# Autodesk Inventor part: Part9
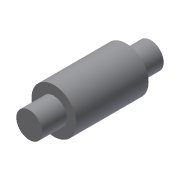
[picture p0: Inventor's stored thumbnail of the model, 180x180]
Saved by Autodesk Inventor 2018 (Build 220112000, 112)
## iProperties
Shininess: 77.0
Length Units: 11269
Angle Units: 11279
Time Units: 11290
Mass Units: 11283
Length Display Precision: 3
Angle Display Precision: 2
Created: 2002-01
Part Number: Part9
Document SubType Name: Modeling
Designer: ***
Density: 1 g/cm^3
Material: Generic
Appearance: Default
Density: 0.0
Volumn: 0.0
Area: 0.0
PropertySet Name: Model Information
Control State: 0
Master: False
Checked Out: False
Author: ***
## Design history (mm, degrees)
sketch "Sketch1"
  geometry: L1 (0.279, 23.245)-(5.19, 23.245); L2 (5.19, 23.245)-(5.19, 13.947); L3 (5.19, 13.947)-(8.761, 13.947); L4 (8.761, 13.947)-(8.761, -13.295); L5 (8.761, -13.295)-(5.19, -13.295); L6 (5.19, -13.295)-(5.19, -22.592); L7 (5.19, -22.592)-(0.279, -22.592); L8 (0.279, -22.592)-(0.279, 23.245)
  constraints: 16 end point, 5 parallel, 2 equal length, 1 collinear, 1 horizontal, 1 perpendicular
revolve "Revolution1" sketch "Sketch1" stored, may be unused: angle "d0" = 90 deg
body "Solid1"
